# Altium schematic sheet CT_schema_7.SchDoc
size 391 x 238 mm
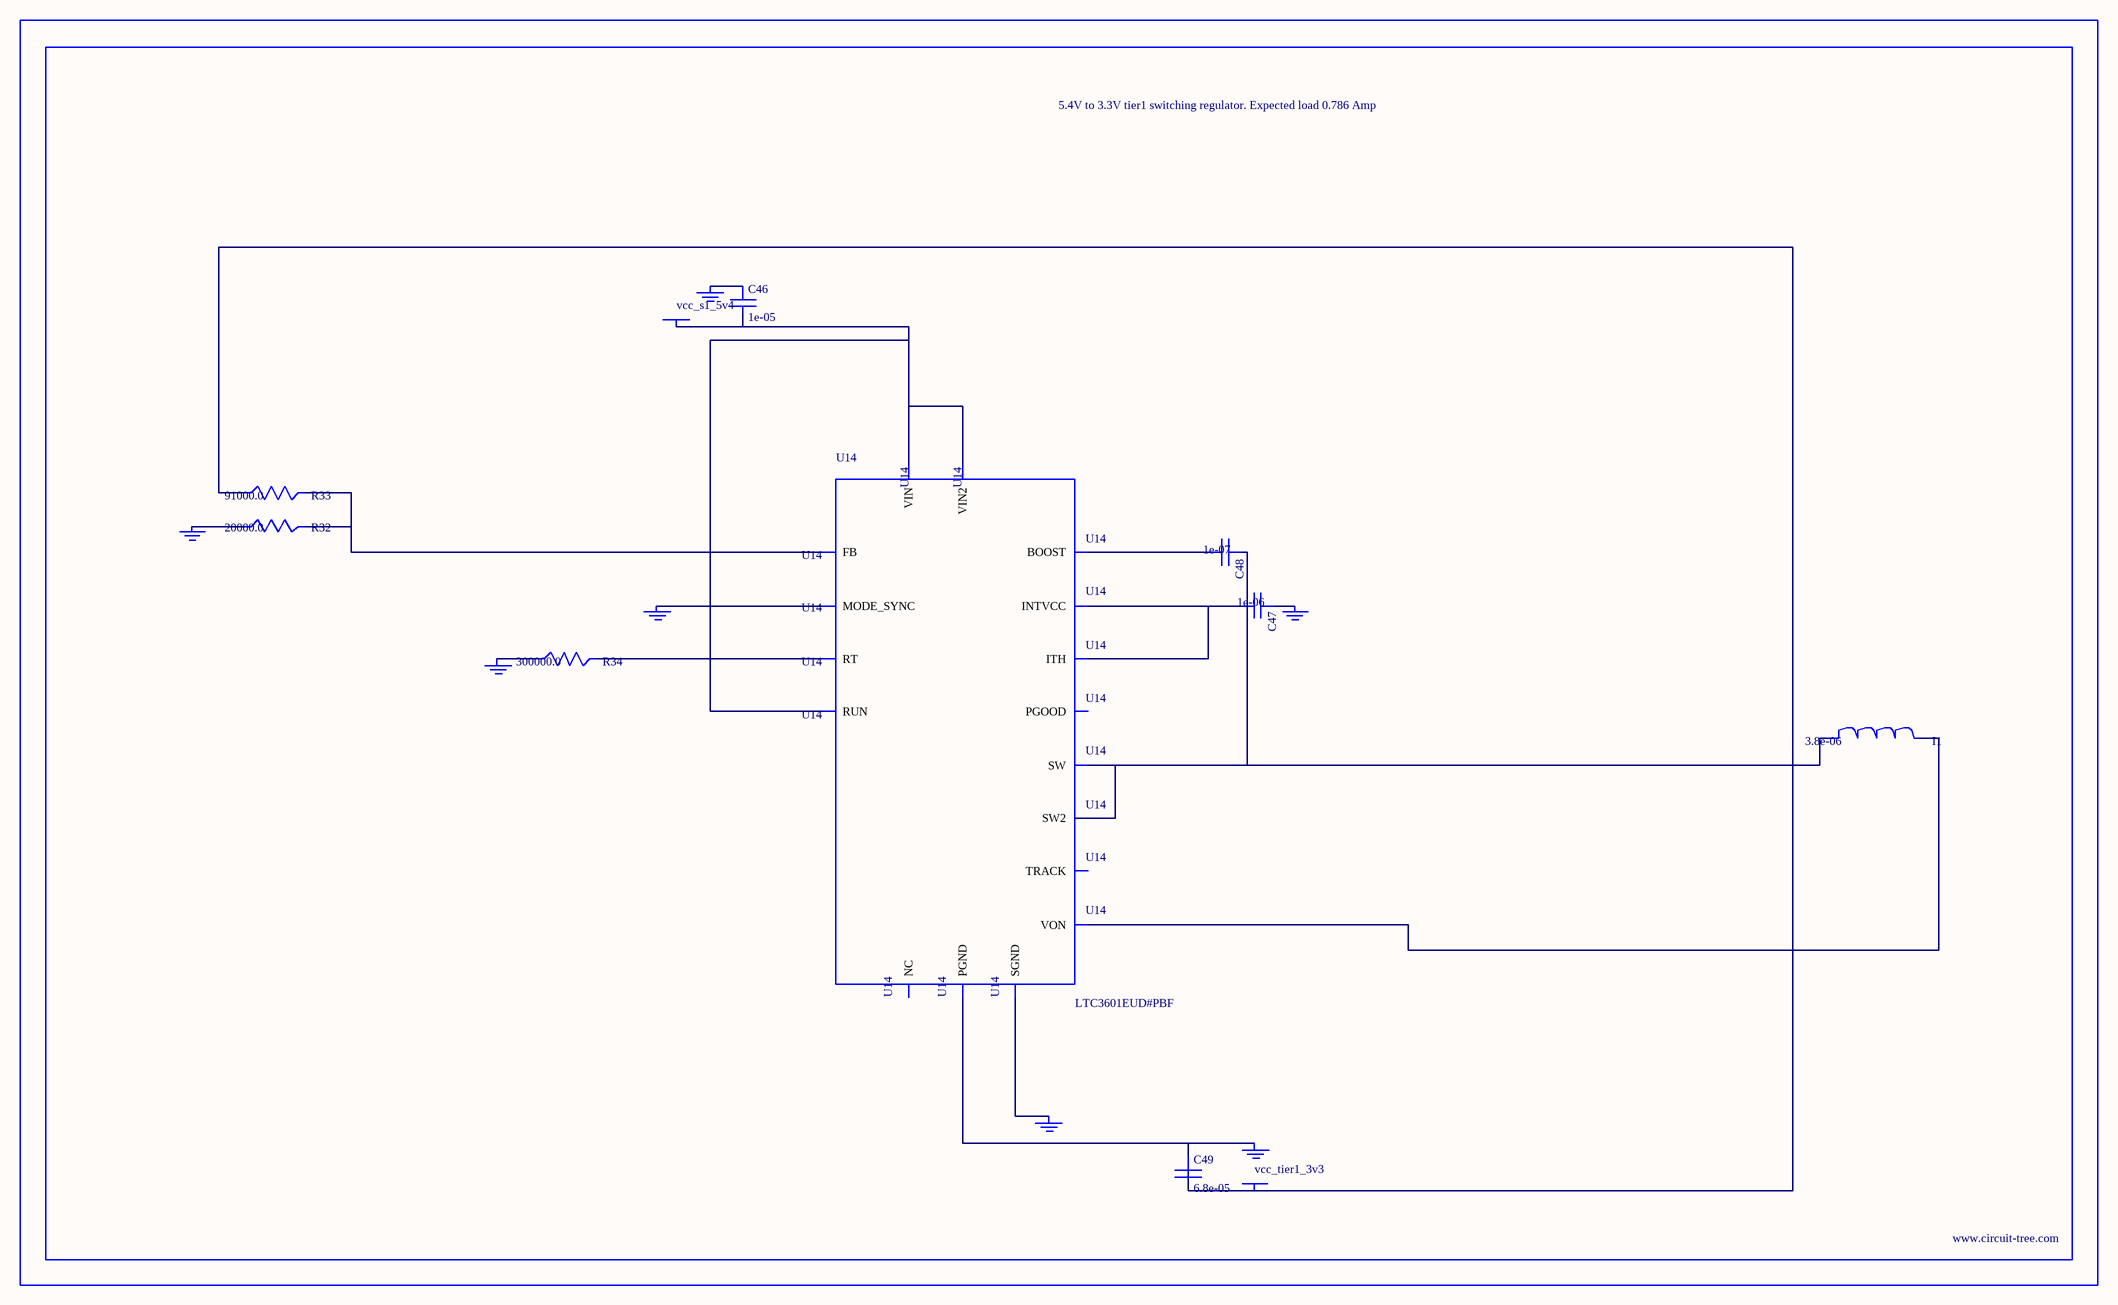
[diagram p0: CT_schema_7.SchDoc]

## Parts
BORDER6  (no value)
C46  1e-05  [C0805]
C47  1e-06  [C0603]
C48  1e-07  [C0402]
C49  6.8e-05  [2220]
GND_INSTANCE_6_0  (no value)
GND_INSTANCE_6_1  (no value)
GND_INSTANCE_6_2  (no value)
GND_INSTANCE_6_3  (no value)
GND_INSTANCE_6_4  (no value)
GND_INSTANCE_6_5  (no value)
GND_INSTANCE_6_6  (no value)
I1  3.8e-06  [DR1040]
POWER_INSTANCE_6_0  vcc_s1_5v4
POWER_INSTANCE_6_1  vcc_tier1_3v3
R32  20000.0  [R0603]
R33  91000.0  [R0603]
R34  300000.0  [R0603]
U14  LTC3601EUD#PBF  [QFN-16_EP]

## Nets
NetC46_1: C46.1 GND_INSTANCE_6_5.0(GND)
NetC46_2: C46.2 POWER_INSTANCE_6_0.0(PWR) U14.14(RUN) U14.15(VIN) U14.16(VIN2)
NetC47_1: C47.1 GND_INSTANCE_6_1.0(GND)
NetC47_2: C47.2 U14.7(INTVCC) U14.12(ITH)
NetC48_1: C48.1 I1.1 U14.3(SW) U14.4(SW2)
NetC48_2: C48.2 U14.6(BOOST)
NetC49_1: C49.1 GND_INSTANCE_6_6.0(GND) U14.17(PGND)
NetC49_2: C49.2 I1.2 POWER_INSTANCE_6_1.0(PWR) R33.1 U14.8(VON)
NetGND_INSTANCE_6_0_0: GND_INSTANCE_6_0.0(GND) U14.1(MODE_SYNC)
NetGND_INSTANCE_6_2_0: GND_INSTANCE_6_2.0(GND) U14.9(SGND)
NetGND_INSTANCE_6_3_0: GND_INSTANCE_6_3.0(GND) R34.1
NetGND_INSTANCE_6_4_0: GND_INSTANCE_6_4.0(GND) R32.1
NetR32_2: R32.2 R33.2 U14.11(FB)
NetR34_2: R34.2 U14.10(RT)

Not connected (* = marked no-connect by the designer): U14 2(PGOOD) 5(NC) 13(TRACK)

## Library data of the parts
BORDER6 = BORDER_PAGE6
C46 = C0805C106K8RACTU
C47 = C0603C105K3RACTU
C48 = C0402C104K3RACTU
C49 = C5750X5R1A686M
GND_INSTANCE_6_0-GND_INSTANCE_6_6 = GND
I1 = DR1040-3R8-R
POWER_INSTANCE_6_0 POWER_INSTANCE_6_1 = PWR
R32 = RC0603JR-0720KL
R33 = RC0603JR-0791KL
R34 = RC0603JR-07300KL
